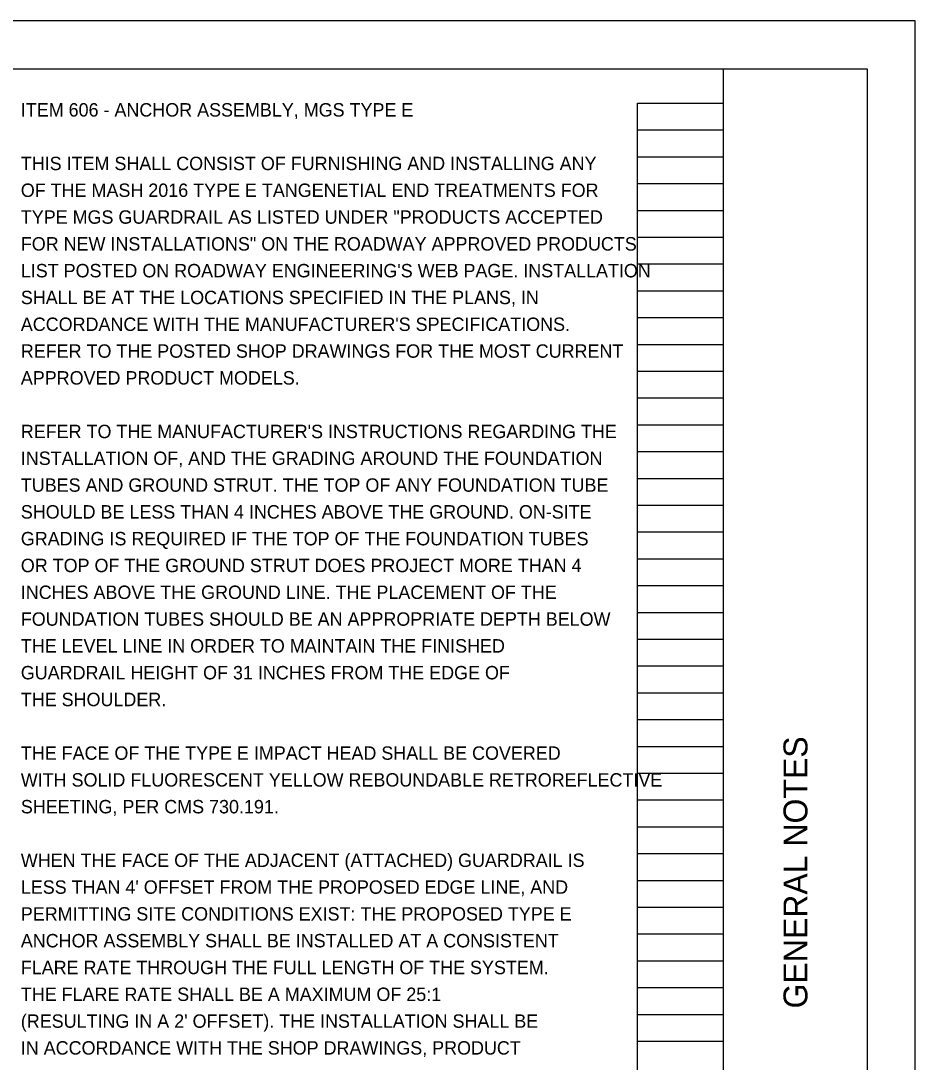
# Model space of a CAD drawing. Extents: x -17.1 to 50.1, y -5.2 to 23.
# Drawn here: x 24.66 to 34, y 11.12 to 22 of the extents above; entities that cross this region are included whole.
import ezdxf

# ---------------------------------------------------------------- set-up
doc = ezdxf.new("R2010")
doc.units = 0
for name, color, linetype in [('SH_Border', 7, 'Continuous'), ('SH_Cut_Line', 7, 'Continuous'), ('SH_Data', 7, 'Continuous'), ('SH_Text', 7, 'Continuous')]:
    doc.layers.add(name, color=color, linetype=linetype)

msp = doc.modelspace()

# ---------------------------------------------------------------- linework, layer by layer
at = {"layer": 'SH_Border'}
msp.add_line((32, 0.5), (32, 21.5), dxfattribs=at)
msp.add_lwpolyline([(1.5, 21.5), (33.5, 21.5), (33.5, 0.5), (1.5, 0.5)], close=True, dxfattribs=at)
at = {"layer": 'SH_Cut_Line'}
msp.add_lwpolyline([(0, 0), (34, 0), (34, 22), (0, 22)], close=True, dxfattribs=at)
at = {"layer": 'SH_Data'}
for p, q in [((31.1, 0.98), (31.1, 21.14)), ((31.1, 21.14), (32, 21.14)), ((32, 0.98), (32, 21.14)), ((31.1, 20.86), (32, 20.86)), ((31.1, 20.58), (32, 20.58)), ((31.1, 20.3), (32, 20.3)), ((31.1, 20.02), (32, 20.02)), ((31.1, 19.74), (32, 19.74)), ((31.1, 19.46), (32, 19.46)), ((31.1, 19.18), (32, 19.18)), ((31.1, 18.9), (32, 18.9)), ((31.1, 18.62), (32, 18.62)), ((31.1, 18.34), (32, 18.34)), ((31.1, 18.06), (32, 18.06)), ((31.1, 17.78), (32, 17.78)), ((31.1, 17.5), (32, 17.5)), ((31.1, 17.22), (32, 17.22)), ((31.1, 16.94), (32, 16.94)), ((31.1, 16.66), (32, 16.66)), ((31.1, 16.38), (32, 16.38)), ((31.1, 16.1), (32, 16.1)), ((31.1, 15.82), (32, 15.82)), ((31.1, 15.54), (32, 15.54)), ((31.1, 15.26), (32, 15.26)), ((31.1, 14.98), (32, 14.98)), ((31.1, 14.7), (32, 14.7)), ((31.1, 14.42), (32, 14.42)), ((31.1, 14.14), (32, 14.14)), ((31.1, 13.86), (32, 13.86)), ((31.1, 13.58), (32, 13.58)), ((31.1, 13.3), (32, 13.3)), ((31.1, 13.02), (32, 13.02)), ((31.1, 12.74), (32, 12.74)), ((31.1, 12.46), (32, 12.46)), ((31.1, 12.18), (32, 12.18)), ((31.1, 11.9), (32, 11.9)), ((31.1, 11.62), (32, 11.62)), ((31.1, 11.34), (32, 11.34))]:
    msp.add_line(p, q, dxfattribs=at)

# ---------------------------------------------------------------- texts
msp.add_text('GENERAL NOTES', height=0.25, rotation=90, dxfattribs=at).set_placement((32.875, 11.682))
at = {"layer": 'SH_Text'}
for s, p in [('ITEM 606 - ANCHOR ASSEMBLY, MGS TYPE E', (24.66, 21)), ('THIS ITEM SHALL CONSIST OF FURNISHING AND INSTALLING ANY', (24.66, 20.44)), ('OF THE MASH 2016 TYPE E TANGENETIAL END TREATMENTS FOR', (24.66, 20.16)), ('TYPE MGS GUARDRAIL AS LISTED UNDER "PRODUCTS ACCEPTED', (24.66, 19.88)), ('FOR NEW INSTALLATIONS" ON THE ROADWAY APPROVED PRODUCTS', (24.66, 19.6)), ("LIST POSTED ON ROADWAY ENGINEERING'S WEB PAGE. INSTALLATION", (24.66, 19.32)), ('SHALL BE AT THE LOCATIONS SPECIFIED IN THE PLANS, IN', (24.66, 19.04)), ("ACCORDANCE WITH THE MANUFACTURER'S SPECIFICATIONS.", (24.66, 18.76)), ('REFER TO THE POSTED SHOP DRAWINGS FOR THE MOST CURRENT', (24.66, 18.48)), ('APPROVED PRODUCT MODELS.', (24.66, 18.2)), ("REFER TO THE MANUFACTURER'S INSTRUCTIONS REGARDING THE", (24.66, 17.64)), ('INSTALLATION OF, AND THE GRADING AROUND THE FOUNDATION', (24.66, 17.36)), ('TUBES AND GROUND STRUT. THE TOP OF ANY FOUNDATION TUBE', (24.66, 17.08)), ('SHOULD BE LESS THAN 4 INCHES ABOVE THE GROUND. ON-SITE', (24.66, 16.8)), ('GRADING IS REQUIRED IF THE TOP OF THE FOUNDATION TUBES', (24.66, 16.52)), ('OR TOP OF THE GROUND STRUT DOES PROJECT MORE THAN 4', (24.66, 16.24)), ('INCHES ABOVE THE GROUND LINE. THE PLACEMENT OF THE', (24.66, 15.96)), ('FOUNDATION TUBES SHOULD BE AN APPROPRIATE DEPTH BELOW', (24.66, 15.68)), ('THE LEVEL LINE IN ORDER TO MAINTAIN THE FINISHED', (24.66, 15.4)), ('GUARDRAIL HEIGHT OF 31 INCHES FROM THE EDGE OF', (24.66, 15.12)), ('THE SHOULDER.', (24.66, 14.84)), ('THE FACE OF THE TYPE E IMPACT HEAD SHALL BE COVERED', (24.66, 14.28)), ('WITH SOLID FLUORESCENT YELLOW REBOUNDABLE RETROREFLECTIVE', (24.66, 14)), ('SHEETING, PER CMS 730.191.', (24.66, 13.72)), ('WHEN THE FACE OF THE ADJACENT (ATTACHED) GUARDRAIL IS', (24.66, 13.16)), ("LESS THAN 4' OFFSET FROM THE PROPOSED EDGE LINE, AND", (24.66, 12.88)), ('PERMITTING SITE CONDITIONS EXIST: THE PROPOSED TYPE E', (24.66, 12.6)), ('ANCHOR ASSEMBLY SHALL BE INSTALLED AT A CONSISTENT', (24.66, 12.32)), ('FLARE RATE THROUGH THE FULL LENGTH OF THE SYSTEM.', (24.66, 12.04)), ('THE FLARE RATE SHALL BE A MAXIMUM OF 25:1', (24.66, 11.76)), ("(RESULTING IN A 2' OFFSET). THE INSTALLATION SHALL BE", (24.66, 11.48)), ('IN ACCORDANCE WITH THE SHOP DRAWINGS, PRODUCT', (24.66, 11.2))]:
    msp.add_text(s, height=0.14, dxfattribs=at).set_placement(p)

doc.saveas('drawing.dxf')
